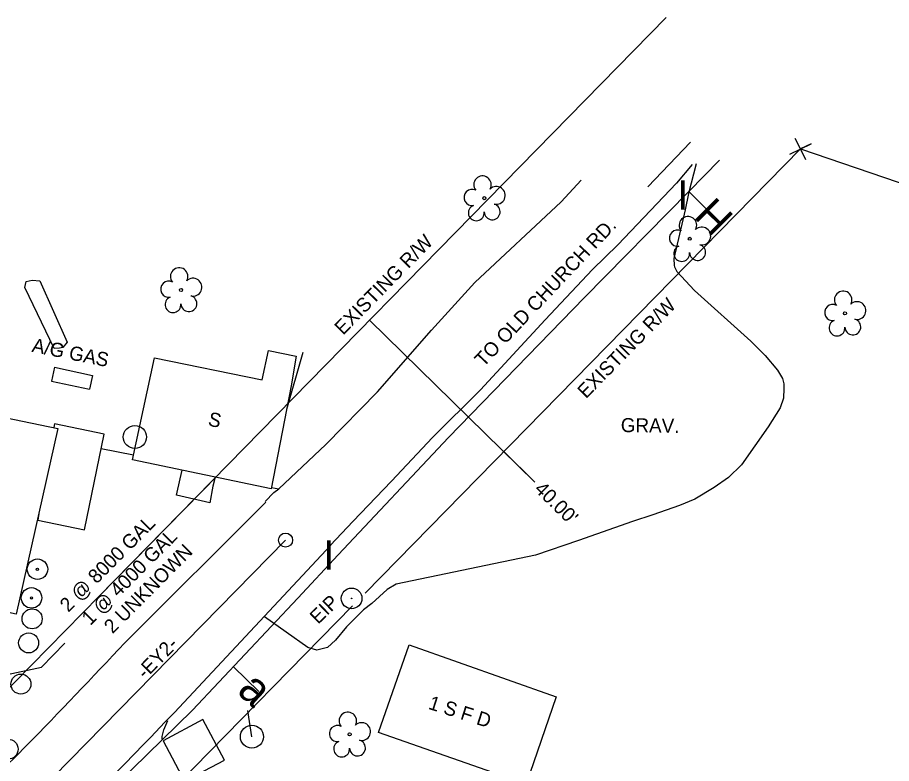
# Model space of a CAD drawing. Extents: x 1645945 to 2447332, y 713118 to 970361.
# Drawn here: x 1646361.8 to 1646547.8, y 969588.4 to 969747.2 of the extents above; entities that cross this region are included whole.
import ezdxf

# ---------------------------------------------------------------- set-up
doc = ezdxf.new("R2010")
doc.units = 0
for name, color, linetype in [('Exist Building', 7, 'Continuous'), ('Exist Building Text', 7, 'Continuous'), ('Exist Horizontal Alignment', 7, 'Continuous'), ('Exist Horizontal Alignment Direction Label', 7, 'Continuous'), ('Exist Horizontal Alignment Station Label', 7, 'Continuous'), ('Exist Other Culture AG Tank', 7, 'Continuous'), ('Exist Other Culture AG Tank Text', 7, 'Continuous'), ('Exist Other Culture Area Outline', 7, 'Continuous'), ('Exist Other Culture Area Outline Leader', 7, 'Continuous'), ('Exist Other Culture Area Outline Text', 7, 'Continuous'), ('Exist Other Culture Located Object CELL', 7, 'Continuous'), ('Exist Other Culture Well CELL', 7, 'Continuous'), ('Exist Property Corner CELL', 7, 'Continuous'), ('Exist Property Iron Pin CELL', 7, 'Continuous'), ('Exist Property Iron Pin Text', 7, 'Continuous'), ('Exist Property Line', 7, 'Continuous'), ('Exist Right of Way Line', 7, 'Continuous'), ('Exist Right of Way Line Text', 7, 'Continuous'), ('Exist Right of Way Width CELL', 7, 'Continuous'), ('Exist Roads EOP', 7, 'Continuous'), ('Exist Roads EOP Leader', 7, 'Continuous'), ('Exist Roads EOP Other', 7, 'Continuous'), ('Exist Roads EOP Text', 7, 'Continuous'), ('Exist Roads Soil', 7, 'Continuous'), ('Exist Roads Soil Text', 7, 'Continuous'), ('Exist Utilities Other Pole CELL', 7, 'Continuous'), ('Exist Utilities Power Pole CELL', 7, 'Continuous'), ('Exist Utilities Water Fire Hydrant CELL', 7, 'Continuous'), ('Exist Utilities Water Meter CELL', 7, 'Continuous'), ('Exist Utilities Water UG Line SUE LOS B', 7, 'Continuous'), ('Exist Utilities Water UG Line SUE LOS C', 7, 'Continuous'), ('Exist Utilities Water Valve CELL', 7, 'Continuous'), ('Exist Vegetation Tree CELL', 7, 'Continuous'), ('Exist Vegetation Woods Line', 7, 'Continuous')]:
    doc.layers.add(name, color=color, linetype=linetype)

msp = doc.modelspace()

# ---------------------------------------------------------------- linework, layer by layer
at = {"layer": 'Exist Building'}
msp.add_line((1646422.46, 969675.92), (1646419.05, 969663.79), dxfattribs=at)
for points in [[(1646262.27, 969682.17), (1646370.37, 969659.74), (1646361.5, 969620.22), (1646334.26, 969626.09), (1646330.25, 969606.95), (1646279.24, 969617.92), (1646283.52, 969637.8), (1646287.23, 969656.4), (1646283.31, 969657.36), (1646281.56, 969650.49), (1646256.7, 969655.82)], [(1646390.89, 969674.8), (1646413.84, 969670.1), (1646415.2, 969676.36), (1646421.05, 969675.09), (1646419.98, 969668.82), (1646415.78, 969646.89), (1646386.21, 969653.03)], [(1646470.02, 969583.99), (1646438.6, 969594.98), (1646445.1, 969613.68), (1646476.38, 969602.62)]]:
    msp.add_lwpolyline(points, close=True, dxfattribs=at)
msp.add_lwpolyline([(1646366.41, 969642.11), (1646366.08, 969640.18), (1646376.05, 969638.17), (1646380.2, 969658.48), (1646369.65, 969660.71), (1646369.52, 969659.91)], dxfattribs=at)
at = {"layer": 'Exist Horizontal Alignment'}
msp.add_line((1646418.81, 969635.96), (1646369.34, 969585.48), dxfattribs=at)
at = {"layer": 'Exist Horizontal Alignment Station Label'}
msp.add_circle((1646418.81, 969635.96), 1.5, dxfattribs=at)
at = {"layer": 'Exist Other Culture AG Tank'}
for p, q in [((1646369.66, 969672.75), (1646369.03, 969669.81)), ((1646369.66, 969672.75), (1646377.74, 969671.02)), ((1646377.74, 969671.02), (1646377.11, 969668.09)), ((1646369.03, 969669.81), (1646377.11, 969668.09))]:
    msp.add_line(p, q, dxfattribs=at)
at = {"layer": 'Exist Other Culture Area Outline'}
msp.add_lwpolyline([(1646403.81, 969649.38), (1646403.35, 969647.47), (1646402.67, 969643.91), (1646395.63, 969645.52), (1646396.41, 969649), (1646396.79, 969650.83)], dxfattribs=at)
msp.add_lwpolyline([(1646397.32, 969584.61), (1646405.82, 969589.12), (1646401.24, 969597.74), (1646392.75, 969593.23), (1646397.32, 969584.61)], close=True, dxfattribs=at)
at = {"layer": 'Exist Other Culture Area Outline Leader'}
msp.add_lwpolyline([(1646348.88, 969605.08), (1646366.88, 969608.89), (1646371.81, 969614)], dxfattribs=at)
at = {"layer": 'Exist Other Culture Located Object CELL'}
for centre, radius in [((1646366.01, 969629.76), 2.18), ((1646366.01, 969629.76), 0.24), ((1646364.75, 969623.65), 2.18), ((1646364.75, 969623.65), 0.24)]:
    msp.add_circle(centre, radius, dxfattribs=at)
at = {"layer": 'Exist Other Culture Well CELL'}
for centre in [(1646364.88, 969619.2), (1646364.14, 969614.07), (1646362.49, 969605.3), (1646359.76, 969591.44)]:
    msp.add_circle(centre, 2.13, dxfattribs=at)
at = {"layer": 'Exist Property Corner CELL'}
msp.add_line((1646528.41, 969719.24), (1646528.41, 969719.24), dxfattribs=at)
msp.add_lwpolyline([(1646526.16, 969718.14), (1646530.65, 969720.34), (1646528.41, 969719.24), (1646527.31, 969721.48), (1646529.51, 969716.99)], dxfattribs=at)
at = {"layer": 'Exist Property Iron Pin CELL'}
for radius in [2.2, 0.0707]:
    msp.add_circle((1646432.87, 969623.55), radius, dxfattribs=at)
at = {"layer": 'Exist Property Line'}
msp.add_line((1646528.41, 969719.24), (1646710.76, 969656.91), dxfattribs=at)
at = {"layer": 'Exist Right of Way Line'}
for p, q in [((1646379, 969623.91), (1646499.84, 969747.23)), ((1646435.76, 969624.69), (1646528.41, 969719.24)), ((1646404.52, 969649.96), (1646355.06, 969599.48)), ((1646433.09, 969621.96), (1646383.63, 969571.48))]:
    msp.add_line(p, q, dxfattribs=at)
at = {"layer": 'Exist Right of Way Width CELL'}
for p in [(1646436.7, 969682.8), (1646465.27, 969654.8)]:
    msp.add_line(p, (1646471.89, 969648.32), dxfattribs=at)
at = {"layer": 'Exist Roads EOP'}
for p, q in [((1646414.62, 969644.03), (1646384.59, 969614.07)), ((1646396.16, 969600.3), (1646428.44, 969634.86))]:
    msp.add_line(p, q, dxfattribs=at)
for points in [[(1646505.34, 969715.95), (1646502.02, 969711.95), (1646489.57, 969698.82)], [(1646414.47, 969644.18), (1646416.34, 969646.07), (1646417.41, 969646.86), (1646427.41, 969656.28), (1646438.37, 969667.54), (1646449.86, 969680.67), (1646459.09, 969690.78), (1646477.51, 969707.96), (1646481.76, 969712.56)], [(1646428.41, 969634.89), (1646433.15, 969639.94), (1646441.35, 969648.53), (1646450.1, 969657.8), (1646460.3, 969667.95), (1646474.07, 969682.88), (1646484.16, 969693.55), (1646489.57, 969698.82)]]:
    msp.add_lwpolyline(points, dxfattribs=at)
for points in [[(1646384.59, 969614.07), (1646363.63, 969592.14), (1646351.92, 969580.65), (1646345.86, 969575.11), (1646339.73, 969569.64), (1646334.58, 969565.16), (1646329.36, 969560.75), (1646318.86, 969552), (1646315.45, 969549.18), (1646312.01, 969546.44), (1646308.49, 969543.75), (1646304.83, 969541.11), (1646302.42, 969539.76), (1646299.77, 969538.9), (1646294.52, 969539.25), (1646282.77, 969544.37), (1646279.95, 969545.5), (1646277.2, 969546.85), (1646276.76, 969547.14)], [(1646373.7, 969456.15), (1646346.78, 969454.01), (1646328.12, 969455.82), (1646313.73, 969464.34), (1646305.52, 969476.97), (1646302.12, 969486.35), (1646303.66, 969500.55), (1646311.37, 969513.37), (1646318.37, 969523.3), (1646325.82, 969532.44), (1646336.85, 969542.47), (1646347.88, 969552.31), (1646363.63, 969567.2), (1646396.16, 969600.3)]]:
    msp.add_spline(points, degree=3, dxfattribs=at)
at = {"layer": 'Exist Roads EOP Leader'}
msp.add_line((1646505, 969720.68), (1646495.94, 969711.2), dxfattribs=at)
at = {"layer": 'Exist Roads EOP Other'}
for p, q in [((1646386.43, 969654.06), (1646379.57, 969655.42)), ((1646417.38, 969646.83), (1646415.82, 969647.11))]:
    msp.add_line(p, q, dxfattribs=at)
at = {"layer": 'Exist Roads Soil'}
for points in [[(1646506.22, 969716.07), (1646504.57, 969709.72), (1646503.86, 969706.28), (1646501.47, 969695.93), (1646501.56, 969694.39), (1646501.61, 969694.11), (1646502.1, 969693.18), (1646505.83, 969689.13), (1646517.84, 969678.34), (1646520.87, 969675.28), (1646523.52, 969672.11), (1646524.56, 969670.34), (1646524.85, 969669.21), (1646524.88, 969668.26), (1646524.79, 969666.2), (1646524.08, 969664.14), (1646521.56, 969660.1), (1646515.83, 969651.96), (1646513.08, 969649.29), (1646510.03, 969647.13), (1646505.89, 969644.67), (1646502.66, 969643.31), (1646496.96, 969641.35), (1646492.63, 969639.9), (1646481.18, 969635.88), (1646472.01, 969632.73), (1646442.39, 969626.55), (1646440.45, 969625.42), (1646437.17, 969622.48), (1646435.38, 969621.09), (1646431.78, 969617.5), (1646429.46, 969614.66), (1646427.71, 969613.1), (1646425.5, 969612.54), (1646423.59, 969613.12), (1646414.32, 969619.64)], [(1646392.56, 969593.54), (1646392.58, 969594.12), (1646392.92, 969595.57), (1646393.73, 969597.56)]]:
    msp.add_lwpolyline(points, dxfattribs=at)
at = {"layer": 'Exist Utilities Other Pole CELL'}
msp.add_circle((1646386.75, 969657.91), 2.46, dxfattribs=at)
at = {"layer": 'Exist Utilities Power Pole CELL'}
for q in [(1646410.82, 969599.66), (1646411.65, 969594.1)]:
    msp.add_line((1646411.65, 969594.1), q, dxfattribs=at)
msp.add_circle((1646411.65, 969594.1), 2.45, dxfattribs=at)
at = {"layer": 'Exist Utilities Water UG Line SUE LOS B'}
msp.add_line((1646504.67, 969710.19), (1646511.14, 969716.85), dxfattribs=at)
msp.add_lwpolyline([(1646353.96, 969554.05), (1646376.58, 969577.81), (1646398.98, 969599.72), (1646421.44, 969623.58), (1646430.02, 969632.82), (1646453.53, 969657.83), (1646482.44, 969687.58), (1646504.67, 969710.19), (1646505.36, 969709.45), (1646509.94, 969704.89)], dxfattribs=at)
at = {"layer": 'Exist Utilities Water UG Line SUE LOS C'}
msp.add_line((1646407.72, 969609), (1646413.13, 969603.73), dxfattribs=at)
at = {"layer": 'Exist Vegetation Tree CELL'}
for p, q in [((1646461.12, 969708.76), (1646461.12, 969708.76)), ((1646504.85, 969700.11), (1646504.85, 969700.11)), ((1646396.57, 969689.21), (1646396.57, 969689.21)), ((1646537.88, 969684.24), (1646537.88, 969684.24)), ((1646432.46, 969594.6), (1646432.46, 969594.6))]:
    msp.add_line(p, q, dxfattribs=at)
for centre in [(1646461.12, 969708.76), (1646504.85, 969700.11), (1646396.57, 969689.21), (1646537.88, 969684.24), (1646432.46, 969594.6)]:
    msp.add_circle(centre, 0.326, dxfattribs=at)
for centre, radius, start, end in [((1646460.73, 969711.63), 1.86, 330.1651, 219.7134), ((1646458.51, 969708.91), 1.73, 62.6636, 279.3457), ((1646463.67, 969709.35), 1.9, 257.1011, 134.1999), ((1646459.41, 969705.64), 1.69, 111.5671, 6.231), ((1646462.79, 969705.86), 1.7, 181.2822, 74.56), ((1646504.46, 969702.98), 1.86, 330.1651, 219.7134), ((1646507.4, 969700.7), 1.9, 257.1011, 134.1999), ((1646502.24, 969700.26), 1.73, 62.6636, 279.3457), ((1646506.52, 969697.21), 1.7, 181.2822, 74.56), ((1646503.14, 969696.99), 1.69, 111.5671, 6.231), ((1646396.18, 969692.09), 1.86, 330.1651, 219.7134), ((1646399.11, 969689.8), 1.9, 257.1011, 134.1999), ((1646393.96, 969689.37), 1.73, 62.6636, 279.3457), ((1646394.86, 969686.09), 1.69, 111.5671, 6.231), ((1646398.24, 969686.31), 1.7, 181.2822, 74.56), ((1646537.5, 969687.12), 1.86, 330.1651, 219.7134), ((1646535.28, 969684.4), 1.73, 62.6636, 279.3457), ((1646540.43, 969684.83), 1.9, 257.1011, 134.1999), ((1646536.18, 969681.12), 1.69, 111.5671, 6.231), ((1646539.55, 969681.34), 1.7, 181.2822, 74.56), ((1646432.07, 969597.47), 1.86, 330.1651, 219.7134), ((1646429.85, 969594.75), 1.73, 62.6636, 279.3457), ((1646435.01, 969595.19), 1.9, 257.1011, 134.1999), ((1646430.75, 969591.48), 1.69, 111.5671, 6.231), ((1646434.13, 969591.7), 1.7, 181.2822, 74.56)]:
    msp.add_arc(centre, radius, start, end, dxfattribs=at)
at = {"layer": 'Exist Vegetation Woods Line'}
msp.add_lwpolyline([(1646363.64, 969691.03), (1646364.88, 969691.31), (1646366.49, 969691.17), (1646372.35, 969678.08), (1646371.4, 969676.94), (1646370.69, 969676.81), (1646369.6, 969676.76), (1646363.35, 969689.73)], close=True, dxfattribs=at)

# ---------------------------------------------------------------- texts
at = {"layer": 'Exist Building Text'}
for s, rotation, p in [('S', 346.9981, (1646402.13, 969660.4)), ('1 S F D', 342.3194, (1646449.03, 969600.06))]:
    msp.add_text(s, height=3, rotation=rotation, dxfattribs=at).set_placement(p)
at = {"layer": 'Exist Horizontal Alignment Direction Label'}
msp.add_text('-EY2-', height=3, rotation=45.5831, dxfattribs=at).set_placement((1646388.97, 969606.22))
at = {"layer": 'Exist Other Culture AG Tank Text'}
msp.add_text('A/G GAS', height=3, rotation=348.5348, dxfattribs=at).set_placement((1646364.67, 969676.07))
at = {"layer": 'Exist Other Culture Area Outline Text'}
for s, p in [('2 @ 8000 GAL', (1646372.58, 969620.45)), ('1 @ 4000 GAL', (1646377.24, 969617.63)), ('2 UNKNOWN', (1646381.99, 969615.88))]:
    msp.add_text(s, height=3, rotation=45.1423, dxfattribs=at).set_placement(p)
at = {"layer": 'Exist Property Iron Pin Text'}
msp.add_text('EIP', height=3, rotation=44.0533, dxfattribs=at).set_placement((1646425.73, 969617.91))
at = {"layer": 'Exist Right of Way Line Text'}
for p in [(1646431.06, 969679.47), (1646482.77, 969665.94)]:
    msp.add_text('EXISTING R/W', height=3, rotation=45.5831, dxfattribs=at).set_placement(p)
at = {"layer": 'Exist Right of Way Width CELL'}
msp.add_text("40.00'", height=3, rotation=315.5831, dxfattribs=at).set_placement((1646471.58, 969646.6))
at = {"layer": 'Exist Roads EOP Text'}
msp.add_text('TO OLD CHURCH RD.', height=3, rotation=46.5794, dxfattribs=at).set_placement((1646460.95, 969672.66))
at = {"layer": 'Exist Roads Soil Text'}
msp.add_text('GRAV.', height=3, rotation=359.1691, dxfattribs=at).set_placement((1646490.15, 969658.96))
at = {"layer": 'Exist Utilities Water Fire Hydrant CELL'}
msp.add_text('H', height=6.51, rotation=135.1393, dxfattribs=at).set_placement((1646514.54, 969704.9))
at = {"layer": 'Exist Utilities Water Meter CELL'}
msp.add_text('a', height=6.89, rotation=317.1266, dxfattribs=at).set_placement((1646408.26, 969603.55))
at = {"layer": 'Exist Utilities Water Valve CELL'}
for p in [(1646502.23, 969706.32), (1646426.89, 969629.69)]:
    msp.add_text('I', height=6.25, dxfattribs=at).set_placement(p)

doc.saveas('drawing.dxf')
